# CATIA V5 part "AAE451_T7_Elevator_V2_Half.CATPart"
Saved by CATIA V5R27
Part number: Elevator
Bounding box of the stored display mesh (mm): x 0 to 69.698, y -12.436 to 0.05, z 0 to 344.945
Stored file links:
  W:\AAE 451\AAE451_T7_TailAssembly_V2\AAE451_T7_Elevator_V2_Half.CATPart
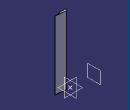
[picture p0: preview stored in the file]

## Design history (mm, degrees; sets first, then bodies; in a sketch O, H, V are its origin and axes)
Set1 "GeometryFromExcel"
  Point1: (1, 0.001, 0)
  Point2: (0.95, 0.0067, 0)
  Point3: (0.9, 0.0121, 0)
  Point4: (0.8, 0.0219, 0)
  Point5: (0.7, 0.0305, 0)
  Point6: (0.6, 0.038, 0)
  Point7: (0.5, 0.0441, 0)
  Point8: (0.4, 0.0484, 0)
  Point9: (0.3, 0.05, 0)
  Point10: (0.25, 0.0495, 0)
  Point11: (0.2, 0.0478, 0)
  Point12: (0.15, 0.0445, 0)
  Point13: (0.1, 0.039, 0)
  Point14: (0.075, 0.035, 0)
  Point15: (0.05, 0.0296, 0)
  Point16: (0.025, 0.0218, 0)
  Point17: (0.0125, 0.0158, 0)
  Point18: (0, 0, 0)
  Point19: (0.0125, -0.0158, 0)
  Point20: (0.025, -0.0218, 0)
  Point21: (0.05, -0.0296, 0)
  Point22: (0.075, -0.035, 0)
  Point23: (0.1, -0.039, 0)
  Point24: (0.15, -0.0445, 0)
  Point25: (0.2, -0.0478, 0)
  Point26: (0.25, -0.0495, 0)
  Point27: (0.3, -0.05, 0)
  Point28: (0.4, -0.0484, 0)
  Point29: (0.5, -0.0441, 0)
  Point30: (0.6, -0.038, 0)
  Point31: (0.7, -0.0305, 0)
  Point32: (0.8, -0.0219, 0)
  Point33: (0.9, -0.0121, 0)
  Point34: (0.95, -0.0067, 0)
  Point35: (1, -0.001, 0)
  Point36: (1, 0.001, 0)
  Point37: (0.95, 0.0067, 0)
  Point38: (0.9, 0.0121, 0)
  Point39: (0.8, 0.0219, 0)
  Point40: (0.7, 0.0305, 0)
  Point41: (0.6, 0.038, 0)
  Point42: (0.5, 0.0441, 0)
  Point43: (0.4, 0.0484, 0)
  Point44: (0.3, 0.05, 0)
  Point45: (0.25, 0.0495, 0)
  Point46: (0.2, 0.0478, 0)
  Point47: (0.15, 0.0445, 0)
  Point48: (0.1, 0.039, 0)
  Point49: (0.075, 0.035, 0)
  Point50: (0.05, 0.0296, 0)
  Point51: (0.025, 0.0218, 0)
  Point52: (0.0125, 0.0158, 0)
  Point53: (0, 0, 0)
  Point54: (0.0125, -0.0158, 0)
  Point55: (0.025, -0.0218, 0)
  Point56: (0.05, -0.0296, 0)
  Point57: (0.075, -0.035, 0)
  Point58: (0.1, -0.039, 0)
  Point59: (0.15, -0.0445, 0)
  Point60: (0.2, -0.0478, 0)
  Point61: (0.25, -0.0495, 0)
  Point62: (0.3, -0.05, 0)
  Point63: (0.4, -0.0484, 0)
  Point64: (0.5, -0.0441, 0)
  Point65: (0.6, -0.038, 0)
  Point66: (0.7, -0.0305, 0)
  Point67: (0.8, -0.0219, 0)
  Point68: (0.9, -0.0121, 0)
  Point69: (0.95, -0.0067, 0)
  Point70: (1, -0.001, 0)
  Curve1: Elements (Point36; Point37; Point38; Point39; Point40; Point41; Point42; Point43; Point44; Point45; Point46; Point47; Point48; Point49; Point50; Point51; Point52; Point53; Point54; Point55; Point56; Point57; Point58; Point59; Point60; Point61; Point62; Point63; Point64; Point65; Point66; Point67; Point68; Point69; Point70)
  Sketch1 on xy-plane, origin (0, 0, 0), H (1, 0, 0), V (0, 1, 0)
    projected curve E1 from edge of Curve1
    point P1 (1, 0.0011)
    line L1 (1, 0.0011) -> (1, -0.001)
    point P3 (1, 0.001)
    point P4 (1, -0.001)
    reference projected point E2 (1, 0.001) from Point1
    reference projected point E3 (1, -0.001) from Point35
    coincidence: P3 E2, P4 E3, P1 P3
Body1 (main body)
  Pad1: profile Sketch1, direction (0, 0, 1), length 1.5215, mirrored extent
  Scaling1: Reference Point40, Ratio 230, ToTransfor Pad1
  Plane1: type Offset, RefPlane yz-plane, Offset 120, reversed
  Sketch2 on xy-plane, origin (0, 0, 0), H (1, 0, 0), V (0, 1, 0)
    reference projected line E1 (69.6979, -7.2245) -> (69.698, -6.7499) from edge [face of Pad1 from Sketch1.L1 | end face of Pad1]
    line L1 (13.6994, -1.0636) -> (13.6965, -12.9194)
    projected curve E2 from edge [face of Pad1 from Sketch1.E1 | end face of Pad1]
    projected curve E3 from edge [face of Pad1 from Sketch1.E1 | end face of Pad1]
    distance E1 L1 = 56
  Pocket1: profile Sketch2, direction (0, 0, -1), through (limit type 3), opposite side through (limit type 3)
  Fillet1: radius 5, on edge [face of Pad1 from Sketch1.E1 | face of Pocket1 from Sketch2.L1]; edge [face of Pocket1 from Sketch2.L1 | face of Pad1 from Sketch1.E1]
  Sketch3 on zx-plane, origin (0, 0, 0), H (-1, 0, 0), V (0, 0, 1)
    line L1 (-135.4649, -344.945) -> (50.2623, -344.945)
    line L2 (50.2623, -344.945) -> (50.2623, -349.945)
    line L3 (50.2623, -349.945) -> (-135.4649, -349.945)
    line L4 (-135.4649, -349.945) -> (-135.4649, -344.945)
    line L5 (-146.4826, 349.945) -> (56.5582, 349.945)
    line L6 (56.5582, 349.945) -> (56.5582, 344.945)
    line L7 (56.5582, 344.945) -> (-146.4826, 344.945)
    line L8 (-146.4826, 344.945) -> (-146.4826, 349.945)
    reference projected line E1 (-69.7, 349.945) -> (160.3, 349.945) from edge [face of Pad1 from Sketch1.E1 | end face of Pad1]
    reference projected line E2 (-69.7, -349.945) -> (160.3, -349.945) from edge [start face of Pad1 | face of Pad1 from Sketch1.E1]
    distance L7 L5 = 5
    horizontal: L1 H, L3 H, L5 H, L7 H
    vertical: L2 V, L4 V, L6 V, L8 V
    coincidence: L5 E1, L3 E2
    symmetry: L7 L1 H
  Pocket2: profile Sketch3, direction (0, -1, 0), through (limit type 3)
  Sketch4 on face of Pocket1 from Sketch2.L1, origin (13.6996, -0.0033, 0), H (-0.0002, -1, 0), V (0, 0, 1)
    line L1 (6.4867, 8) -> (7.4867, 8)
    line L2 (7.4867, 8) -> (7.4867, -8)
    line L3 (7.4867, -8) -> (6.4867, -8)
    line L4 (6.4867, -8) -> (6.4867, 8)
    construction line L5 (6.9867, 7.1913) -> (6.9867, -6.7162)
    reference projected line E1 (1.5418, 344.945) -> (1.5418, -344.945) from edge [face of Pad1 from Sketch1.E1 | face of Fillet1]
    reference projected line E2 (12.4317, 344.945) -> (12.4317, -344.945) from edge [face of Fillet1 | face of Pad1 from Sketch1.E1]
    distance L4 L2 = 1
    distance L1 L3 = 16
    horizontal: L1 H, L3 H
    vertical: L2 V, L4 V
    symmetry: L3 L1 H, L4 L2 L5, E1 E2 L5
  Pocket3: profile Sketch4, direction (1, -0.0002, 0), length 13.7
  RectPattern1: of Pocket3, direction 1 instances 2, spacing 230, along zx-plane
  Mirror1: of RectPattern1, about xy-plane
  Split1: SplitPlane xy-plane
